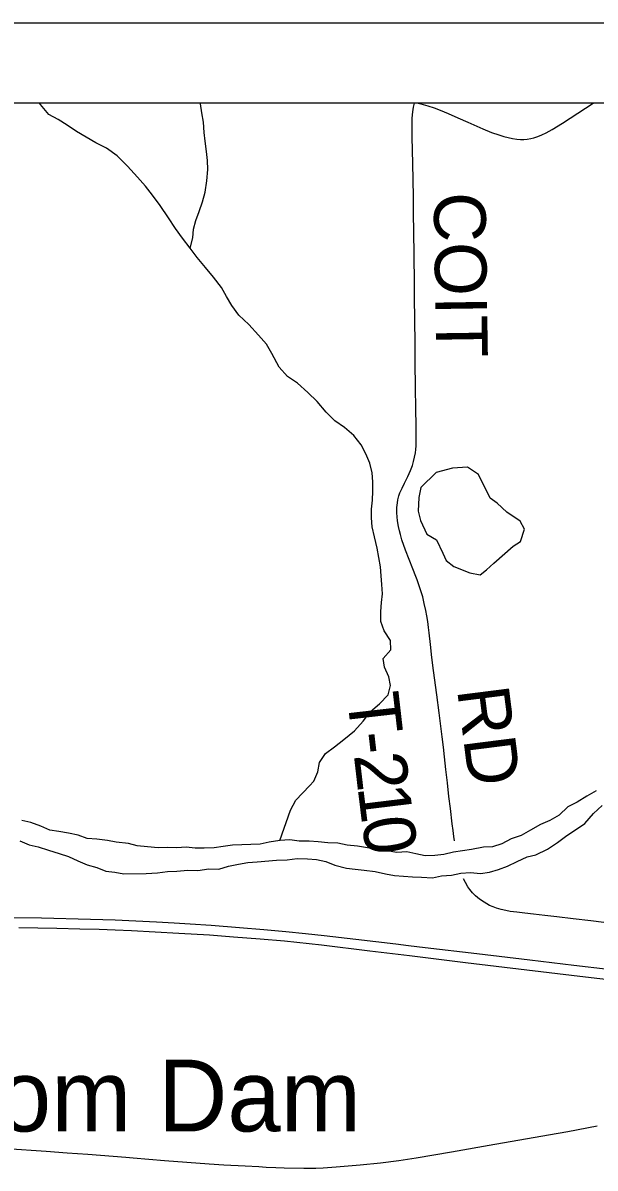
# Model space of a CAD drawing. Extents: x 0 to 34, y 0 to 22.
# Drawn here: x 14.178 to 14.807, y 15.551 to 16.81 of the extents above; entities that cross this region are included whole.
import ezdxf

# ---------------------------------------------------------------- set-up
doc = ezdxf.new("R2010")
doc.units = 0
for name, color, linetype in [('GM_X_Corporation', 7, 'Continuous'), ('GM_X_Interstate_Route', 7, 'Continuous'), ('GM_X_Major_River', 7, 'Continuous'), ('GM_X_Minor_Lake', 7, 'Continuous'), ('GM_X_Minor_River', 7, 'Continuous'), ('GM_X_State_Route', 7, 'Continuous'), ('GM_X_Township_Road', 7, 'Continuous'), ('GM_X_Township_Road_Text', 7, 'Continuous'), ('GM_X_Unincorporated_Text', 7, 'Continuous'), ('SH_Data', 7, 'Continuous')]:
    doc.layers.add(name, color=color, linetype=linetype)

msp = doc.modelspace()

# ---------------------------------------------------------------- linework, layer by layer
at = {"layer": 'GM_X_Corporation'}
msp.add_lwpolyline([(18.6549, 16.7214), (13.0992, 16.7214)], dxfattribs=at)
at = {"layer": 'GM_X_Interstate_Route'}
for points in [[(14.1321, 15.8267), (14.1983, 15.8257), (14.2522, 15.8245), (14.2793, 15.8237), (14.3021, 15.8226), (14.3247, 15.8216), (14.3441, 15.8204), (14.3618, 15.8193), (14.3847, 15.8178), (14.4158, 15.8154), (14.4427, 15.8132), (14.467, 15.8109), (14.4886, 15.8086), (14.5088, 15.8064), (14.5438, 15.8023), (14.5876, 15.7971), (14.6016, 15.7955), (14.6199, 15.7933), (14.6767, 15.7866), (14.7351, 15.7798), (14.7834, 15.7738), (14.8586, 15.765)], [(14.1734, 15.8153), (14.2154, 15.8146), (14.2405, 15.8139), (14.2616, 15.8133), (14.2793, 15.8128), (14.2973, 15.812), (14.3492, 15.8091), (14.3828, 15.8071), (14.4092, 15.8049), (14.4388, 15.8027), (14.4652, 15.8005), (14.5062, 15.7963), (14.559, 15.7897), (14.6028, 15.7846), (14.6642, 15.7769), (14.7897, 15.7619), (14.8619, 15.7532)]]:
    msp.add_lwpolyline(points, dxfattribs=at)
at = {"layer": 'GM_X_Major_River'}
for points in [[(14.8077, 15.9655), (14.7975, 15.9597), (14.787, 15.9532), (14.7768, 15.9478), (14.767, 15.9386), (14.7568, 15.9329), (14.7467, 15.9286), (14.7357, 15.9221), (14.7256, 15.9163), (14.7146, 15.9128), (14.7041, 15.9071), (14.6939, 15.9039), (14.684, 15.9035), (14.6708, 15.9011), (14.661, 15.8995), (14.6511, 15.8979), (14.6406, 15.8956), (14.6304, 15.8944), (14.6201, 15.8939), (14.6095, 15.8961), (14.5997, 15.8983), (14.5887, 15.8978), (14.5781, 15.8996), (14.5667, 15.9007), (14.5565, 15.9029), (14.5455, 15.9047), (14.5341, 15.9058), (14.5239, 15.908), (14.5129, 15.9083), (14.5023, 15.9093), (14.4925, 15.91), (14.4815, 15.9103), (14.4712, 15.9117), (14.4603, 15.9109), (14.4486, 15.9089), (14.4387, 15.9069), (14.4081, 15.9056), (14.3979, 15.9043), (14.388, 15.9027), (14.3771, 15.9023), (14.3672, 15.9026), (14.3574, 15.9037), (14.3472, 15.9028), (14.337, 15.9031), (14.3267, 15.903), (14.315, 15.9041), (14.3036, 15.9051), (14.2938, 15.9077), (14.2805, 15.9091), (14.271, 15.911), (14.2593, 15.9124), (14.2487, 15.9131), (14.2388, 15.9168), (14.2282, 15.919), (14.2176, 15.9208), (14.2077, 15.9222), (14.1975, 15.9267), (14.1865, 15.9308), (14.1766, 15.933)], [(14.1745, 15.9106), (14.1848, 15.9062), (14.1947, 15.904), (14.2061, 15.9003), (14.2179, 15.8967), (14.2281, 15.8934), (14.2384, 15.8886), (14.2487, 15.8841), (14.259, 15.8812), (14.2689, 15.8771), (14.2791, 15.8761), (14.289, 15.8743), (14.3132, 15.8746), (14.3257, 15.8755), (14.337, 15.8768), (14.3469, 15.8773), (14.359, 15.8782), (14.3703, 15.8779), (14.3821, 15.8796), (14.3934, 15.8794), (14.404, 15.8825), (14.415, 15.8849), (14.4252, 15.8866), (14.4354, 15.8874), (14.4566, 15.8892), (14.4683, 15.8897), (14.4793, 15.891), (14.4906, 15.8907), (14.5005, 15.8901), (14.5108, 15.8879), (14.5206, 15.8839), (14.5336, 15.8806), (14.543, 15.8792), (14.5529, 15.8782), (14.565, 15.8768), (14.5764, 15.8743), (14.5863, 15.8725), (14.5962, 15.8715), (14.606, 15.8708), (14.6159, 15.8706), (14.628, 15.8699), (14.6378, 15.872), (14.6488, 15.8728), (14.659, 15.8749), (14.6696, 15.8757), (14.6806, 15.8747), (14.6908, 15.876), (14.7006, 15.8791), (14.7104, 15.8827), (14.721, 15.8877), (14.7319, 15.8928), (14.7417, 15.8952), (14.7545, 15.9014), (14.7654, 15.9088), (14.7756, 15.9165), (14.7853, 15.9227), (14.7955, 15.9296), (14.8048, 15.9404), (14.8146, 15.9492)]]:
    msp.add_lwpolyline(points, dxfattribs=at)
at = {"layer": 'GM_X_Minor_Lake'}
msp.add_line((14.6954, 16.2157), (14.7165, 16.2344), dxfattribs=at)
msp.add_lwpolyline([(14.7165, 16.2344), (14.7248, 16.2397), (14.7289, 16.2531), (14.7243, 16.2618), (14.7095, 16.2719), (14.6992, 16.2817), (14.6912, 16.2874), (14.6786, 16.3131), (14.6664, 16.3214), (14.6501, 16.3202), (14.632, 16.3156), (14.615, 16.2988), (14.6128, 16.2881), (14.6121, 16.273), (14.6148, 16.2627), (14.6217, 16.2476), (14.6323, 16.2416), (14.6392, 16.2268), (14.643, 16.2188), (14.6514, 16.2121), (14.6689, 16.2053), (14.6803, 16.2031), (14.6874, 16.2084), (14.6954, 16.2157)], dxfattribs=at)
at = {"layer": 'GM_X_Minor_River'}
for points in [[(14.4927, 15.971), (14.4975, 15.976), (14.502, 15.9863), (14.5038, 15.9965), (14.5106, 16.0064), (14.5204, 16.0137), (14.5306, 16.0221), (14.5423, 16.0316), (14.5518, 16.0419), (14.56, 16.0526), (14.5699, 16.061), (14.5793, 16.0709), (14.5819, 16.0812), (14.58, 16.091), (14.5754, 16.1016), (14.5738, 16.1111), (14.5821, 16.1206), (14.5817, 16.1309), (14.5748, 16.1415), (14.5713, 16.1517), (14.5713, 16.1627), (14.572, 16.1726), (14.5731, 16.1821), (14.5723, 16.1923), (14.5715, 16.2018), (14.5707, 16.2117), (14.5691, 16.2219), (14.5672, 16.2321), (14.5641, 16.2446), (14.5617, 16.2556), (14.5609, 16.2655), (14.5609, 16.275), (14.562, 16.2852), (14.5623, 16.2951), (14.5623, 16.3053), (14.5618, 16.3152), (14.5591, 16.3258), (14.5549, 16.336), (14.5496, 16.3459), (14.5416, 16.3561), (14.5313, 16.3648), (14.5206, 16.3723), (14.5111, 16.3817), (14.5012, 16.3935), (14.4909, 16.4036), (14.4795, 16.4135), (14.4685, 16.421), (14.4597, 16.4312), (14.4513, 16.4463), (14.4456, 16.4565), (14.4368, 16.4664), (14.4261, 16.4781), (14.4151, 16.4886), (14.4075, 16.4989), (14.4017, 16.5091), (14.396, 16.5189), (14.3872, 16.5302), (14.3785, 16.5408), (14.3693, 16.5518), (14.3617, 16.562), (14.3533, 16.573), (14.3457, 16.5839), (14.338, 16.5956), (14.3289, 16.6089), (14.3205, 16.6202), (14.3125, 16.6301), (14.3037, 16.6403), (14.293, 16.6523), (14.2816, 16.6637), (14.2698, 16.672), (14.258, 16.678), (14.2474, 16.684), (14.2367, 16.6904), (14.2265, 16.6972), (14.2166, 16.7036), (14.2063, 16.7092), (14.1972, 16.7202), (14.1961, 16.7214)], [(14.3617, 16.562), (14.3647, 16.5734), (14.3654, 16.5829), (14.368, 16.5924), (14.3717, 16.6023), (14.3751, 16.6129), (14.3781, 16.6236), (14.3799, 16.6361), (14.381, 16.6486), (14.3809, 16.6585), (14.3798, 16.6683), (14.3782, 16.6797), (14.377, 16.6892), (14.3762, 16.7006), (14.3746, 16.7108), (14.3731, 16.7207), (14.373, 16.7214)], [(14.4602, 15.9109), (14.4721, 15.9444), (14.4778, 15.9552), (14.4927, 15.971)]]:
    msp.add_lwpolyline(points, dxfattribs=at)
at = {"layer": 'GM_X_State_Route'}
for points in [[(14.2991, 15.562), (14.3335, 15.5591), (14.3826, 15.5554), (14.3987, 15.5544), (14.4222, 15.5531), (14.4371, 15.5523), (14.4451, 15.5518), (14.4557, 15.5513), (14.465, 15.5511), (14.4867, 15.5507), (14.4997, 15.5508), (14.5078, 15.5511), (14.522, 15.552), (14.5486, 15.5544), (14.5708, 15.5566), (14.5911, 15.5592), (14.6102, 15.5621), (14.6488, 15.5687), (14.6965, 15.577), (14.7659, 15.5892)], [(14.7659, 15.5892), (14.7767, 15.5911), (14.8091, 15.597)], [(14.1598, 15.5723), (14.2035, 15.5692), (14.2265, 15.5676), (14.2492, 15.566), (14.2911, 15.5626), (14.2991, 15.562)]]:
    msp.add_lwpolyline(points, dxfattribs=at)
at = {"layer": 'GM_X_Township_Road'}
for points in [[(14.6521, 15.9106), (14.6515, 15.9154), (14.6506, 15.9217), (14.6497, 15.9293), (14.6477, 15.9459), (14.6461, 15.9594), (14.6444, 15.9741), (14.6428, 15.989), (14.6412, 16.0029), (14.6401, 16.0135), (14.6388, 16.0249), (14.6354, 16.0512), (14.6327, 16.0712), (14.6292, 16.0978), (14.6274, 16.1119), (14.6258, 16.1265), (14.6244, 16.1391), (14.6237, 16.1451), (14.6228, 16.1518), (14.6218, 16.1579), (14.6207, 16.1637), (14.6189, 16.1716), (14.6173, 16.1786), (14.6152, 16.1852), (14.6128, 16.1921), (14.611, 16.1974), (14.6097, 16.2011), (14.6063, 16.2094), (14.5984, 16.23), (14.5944, 16.2414), (14.5927, 16.2472), (14.5916, 16.2515), (14.5905, 16.2562), (14.5895, 16.2624), (14.589, 16.2666), (14.5888, 16.2712), (14.5889, 16.2771), (14.5894, 16.282), (14.5899, 16.2854), (14.5909, 16.2897), (14.5921, 16.2931), (14.5945, 16.2983), (14.5974, 16.3039), (14.6008, 16.3109), (14.6038, 16.3177), (14.6059, 16.3233), (14.6072, 16.3274), (14.6084, 16.3324), (14.6092, 16.337), (14.6096, 16.3408), (14.6099, 16.3449), (14.6099, 16.349), (14.6099, 16.3562), (14.6099, 16.3629), (14.6096, 16.3895), (14.6094, 16.405), (14.6089, 16.4404), (14.6088, 16.4594), (14.6086, 16.4812), (14.6084, 16.5101), (14.6082, 16.5243), (14.6079, 16.5541), (14.6075, 16.5807), (14.6072, 16.5994), (14.607, 16.619), (14.6063, 16.6552), (14.6057, 16.6841), (14.6056, 16.6927), (14.6056, 16.6983), (14.6057, 16.7045), (14.606, 16.7086), (14.6064, 16.712), (14.6073, 16.7172), (14.6081, 16.7214)], [(14.6124, 16.7214), (14.6152, 16.7207), (14.6227, 16.7186), (14.6297, 16.7163), (14.6363, 16.7138), (14.6452, 16.7102), (14.6559, 16.7055), (14.6669, 16.7007), (14.6833, 16.6934), (14.6928, 16.6894), (14.7007, 16.6867), (14.7064, 16.685), (14.711, 16.6837), (14.7159, 16.6826), (14.7205, 16.682), (14.7246, 16.6817), (14.7284, 16.6817), (14.732, 16.682), (14.7359, 16.6826), (14.7395, 16.6835), (14.7437, 16.6848), (14.748, 16.6866), (14.7529, 16.6889), (14.7593, 16.6925), (14.7709, 16.6997), (14.8047, 16.7214)], [(14.8162, 15.8208), (14.8018, 15.8227), (14.7827, 15.8248), (14.7646, 15.827), (14.7513, 15.8286), (14.7389, 15.83), (14.7293, 15.831), (14.7207, 15.8321), (14.7133, 15.833), (14.7084, 15.8338), (14.7035, 15.835), (14.6983, 15.8366), (14.6945, 15.8379), (14.6906, 15.8396), (14.6846, 15.8429), (14.6796, 15.8463), (14.6753, 15.85), (14.6719, 15.8534), (14.6689, 15.8571), (14.6669, 15.86), (14.6641, 15.8646), (14.662, 15.8688)]]:
    msp.add_lwpolyline(points, dxfattribs=at)
at = {"layer": 'SH_Data'}
msp.add_line((12.556, 16.8098), (19.556, 16.8098), dxfattribs=at)

# ---------------------------------------------------------------- texts
at = {"layer": 'GM_X_Township_Road_Text'}
for s, height, rotation, p in [('COIT', 0.05682, 270.8717, (14.6293, 16.6232)), ('T', 0.0568, 276.5584, (14.5339, 16.0705)), ('RD', 0.05682, 277.2438, (14.6549, 16.077)), ('-', 0.0568, 276.5622, (14.5388, 16.0283)), ('2', 0.0568, 276.6648, (14.5415, 16.005)), ('1', 0.0568, 276.9817, (14.5456, 15.9699)), ('0', 0.0568, 277.9366, (14.55, 15.9341))]:
    msp.add_text(s, height=height, rotation=rotation, dxfattribs=at).set_placement(p)
at = {"layer": 'GM_X_Unincorporated_Text'}
msp.add_text('Freedom Dam', height=0.078977, rotation=0, dxfattribs=at).set_placement((13.8744, 15.591))

doc.saveas('drawing.dxf')
